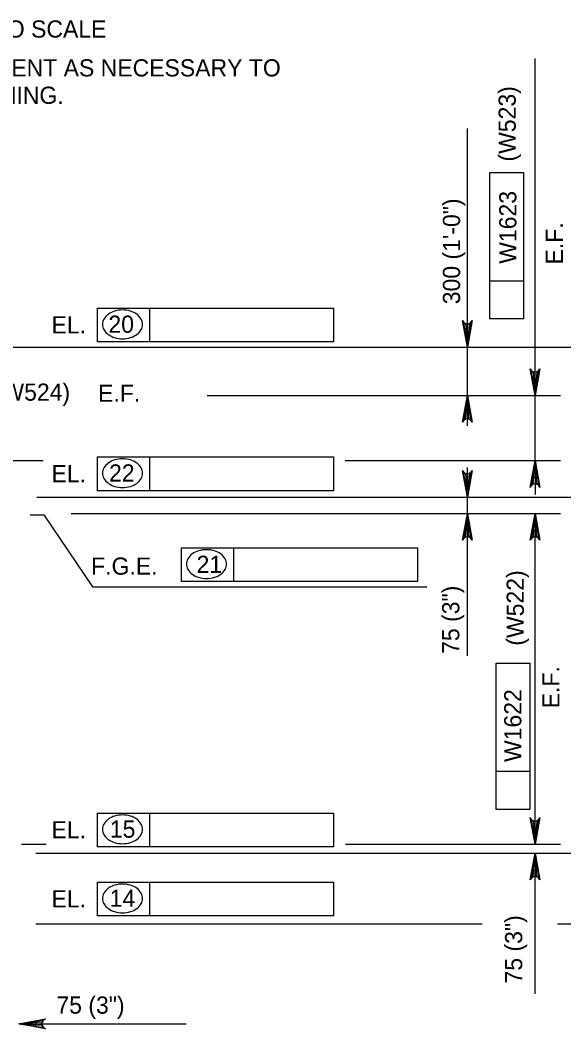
# Model space of a CAD drawing. Extents: x 634540 to 640306, y 296059 to 300275.
# Drawn here: x 639745.6 to 639840.5, y 297355.8 to 297531.8 of the extents above; entities that cross this region are included whole.
import ezdxf

# ---------------------------------------------------------------- set-up
doc = ezdxf.new("R2010")
doc.units = 0
doc.layers.add('3', color=7, linetype='Continuous')
doc.layers.add('4', color=7, linetype='Continuous')

msp = doc.modelspace()

# ---------------------------------------------------------------- linework, layer by layer
at = {"layer": '3'}
msp.add_line((639747.39, 297445.53), (639749.79, 297445.53), dxfattribs=at)
at = {"layer": '4'}
for p, q in [((639835.5, 297476.96), (639835.5, 297525.13)), ((639823.69, 297461.05), (639823.69, 297512.93)), ((639827.61, 297479.7), (639827.61, 297505.24)), ((639827.61, 297505.24), (639833.52, 297505.24)), ((639833.52, 297505.24), (639833.52, 297479.7)), ((639833.52, 297486.29), (639827.61, 297486.29)), ((639759.12, 297481.58), (639800.33, 297481.58)), ((639759.12, 297475.68), (639759.12, 297481.58)), ((639768.29, 297475.68), (639768.29, 297481.58)), ((639800.33, 297481.58), (639800.33, 297475.68)), ((639833.52, 297479.7), (639827.61, 297479.7)), ((639835.5, 297469.29), (639835.5, 297476.96)), ((639676.62, 297474.75), (639870.77, 297474.75)), ((639800.33, 297475.68), (639759.12, 297475.68)), ((639778.3, 297466.33), (639839.93, 297466.33)), ((639835.5, 297454.96), (639835.5, 297466.33)), ((639759.12, 297455.62), (639800.33, 297455.62)), ((639759.12, 297449.71), (639759.12, 297455.62)), ((639768.29, 297449.71), (639768.29, 297455.62)), ((639800.33, 297455.62), (639800.33, 297449.71)), ((639735.66, 297454.96), (639749.63, 297454.96)), ((639802.35, 297454.96), (639839.93, 297454.96)), ((639823.69, 297420.89), (639823.69, 297453.79)), ((639835.5, 297452.01), (639835.5, 297449.06)), ((639748.53, 297448.6), (639858.89, 297448.6)), ((639800.33, 297449.71), (639759.12, 297449.71)), ((639749.79, 297445.53), (639758.26, 297432.92)), ((639754.55, 297445.73), (639839.93, 297445.73)), ((639835.5, 297390.96), (639835.5, 297442.78)), ((639773.78, 297433.85), (639773.78, 297439.76)), ((639773.78, 297439.76), (639814.99, 297439.76)), ((639782.95, 297433.85), (639782.95, 297439.76)), ((639814.99, 297439.76), (639814.99, 297433.85)), ((639758.26, 297432.92), (639816.6, 297432.92)), ((639814.99, 297433.85), (639773.78, 297433.85)), ((639828.7, 297394.11), (639828.7, 297419.65)), ((639828.7, 297419.65), (639834.61, 297419.65)), ((639834.61, 297419.65), (639834.61, 297394.11)), ((639834.61, 297400.7), (639828.7, 297400.7)), ((639834.61, 297394.11), (639828.7, 297394.11)), ((639759.12, 297393.47), (639800.33, 297393.47)), ((639759.12, 297387.57), (639759.12, 297393.47)), ((639768.29, 297387.57), (639768.29, 297393.47)), ((639800.33, 297393.47), (639800.33, 297387.57)), ((639745.89, 297388.01), (639750.16, 297388.01)), ((639800.33, 297387.57), (639759.12, 297387.57)), ((639802.41, 297388.01), (639839.93, 297388.01)), ((639748.37, 297386.47), (639870.77, 297386.47)), ((639835.5, 297361.91), (639835.5, 297383.52)), ((639759.12, 297381.42), (639800.33, 297381.42)), ((639759.12, 297375.51), (639759.12, 297381.42)), ((639768.29, 297375.51), (639768.29, 297381.42)), ((639800.33, 297381.42), (639800.33, 297375.51)), ((639800.33, 297375.51), (639759.12, 297375.51)), ((639748.37, 297374.16), (639826.28, 297374.16)), ((639839.41, 297374.16), (639870.77, 297374.16)), ((639748.33, 297356.69), (639751.28, 297356.69)), ((639751.28, 297356.69), (639774.6, 297356.69))]:
    msp.add_line(p, q, dxfattribs=at)
for points in [[(639823.69, 297474.75), (639822.82, 297479.41), (639823.06, 297479.05), (639823.38, 297478.86), (639823.69, 297478.81), (639824, 297478.86), (639824.32, 297479.05), (639824.56, 297479.41), (639823.69, 297474.75), (639824.32, 297479.05), (639824, 297478.86), (639823.69, 297474.75), (639823.69, 297478.81), (639823.38, 297478.86), (639823.69, 297474.75), (639823.06, 297479.05)], [(639835.5, 297466.33), (639834.63, 297470.99), (639834.88, 297470.64), (639835.19, 297470.45), (639835.5, 297470.4), (639835.81, 297470.45), (639836.13, 297470.64), (639836.37, 297470.99), (639835.5, 297466.33), (639836.13, 297470.64), (639835.81, 297470.45), (639835.5, 297466.33), (639835.5, 297470.4), (639835.19, 297470.45), (639835.5, 297466.33), (639834.88, 297470.64)], [(639823.69, 297466.33), (639824.56, 297461.67), (639824.32, 297462.03), (639824, 297462.22), (639823.69, 297462.27), (639823.38, 297462.22), (639823.06, 297462.03), (639822.82, 297461.67), (639823.69, 297466.33), (639823.06, 297462.03), (639823.38, 297462.22), (639823.69, 297466.33), (639823.69, 297462.27), (639824, 297462.22), (639823.69, 297466.33), (639824.32, 297462.03)], [(639835.5, 297454.96), (639836.37, 297450.3), (639836.13, 297450.66), (639835.81, 297450.85), (639835.5, 297450.9), (639835.19, 297450.85), (639834.88, 297450.66), (639834.63, 297450.3), (639835.5, 297454.96), (639834.88, 297450.66), (639835.19, 297450.85), (639835.5, 297454.96), (639835.5, 297450.9), (639835.81, 297450.85), (639835.5, 297454.96), (639836.13, 297450.66)], [(639823.69, 297448.6), (639822.82, 297453.26), (639823.06, 297452.9), (639823.38, 297452.72), (639823.69, 297452.66), (639824, 297452.72), (639824.32, 297452.9), (639824.56, 297453.26), (639823.69, 297448.6), (639824.32, 297452.9), (639824, 297452.72), (639823.69, 297448.6), (639823.69, 297452.66), (639823.38, 297452.72), (639823.69, 297448.6), (639823.06, 297452.9)], [(639823.69, 297445.73), (639824.56, 297441.07), (639824.32, 297441.43), (639824, 297441.62), (639823.69, 297441.67), (639823.38, 297441.62), (639823.06, 297441.43), (639822.82, 297441.07), (639823.69, 297445.73), (639823.06, 297441.43), (639823.38, 297441.62), (639823.69, 297445.73), (639823.69, 297441.67), (639824, 297441.62), (639823.69, 297445.73), (639824.32, 297441.43)], [(639835.5, 297445.73), (639836.37, 297441.07), (639836.13, 297441.43), (639835.81, 297441.62), (639835.5, 297441.67), (639835.19, 297441.62), (639834.88, 297441.43), (639834.63, 297441.07), (639835.5, 297445.73), (639834.88, 297441.43), (639835.19, 297441.62), (639835.5, 297445.73), (639835.5, 297441.67), (639835.81, 297441.62), (639835.5, 297445.73), (639836.13, 297441.43)], [(639835.5, 297388.01), (639834.63, 297392.67), (639834.88, 297392.31), (639835.19, 297392.12), (639835.5, 297392.07), (639835.81, 297392.12), (639836.13, 297392.31), (639836.37, 297392.67), (639835.5, 297388.01), (639836.13, 297392.31), (639835.81, 297392.12), (639835.5, 297388.01), (639835.5, 297392.07), (639835.19, 297392.12), (639835.5, 297388.01), (639834.88, 297392.31)], [(639835.5, 297386.47), (639836.37, 297381.81), (639836.13, 297382.17), (639835.81, 297382.35), (639835.5, 297382.4), (639835.19, 297382.35), (639834.88, 297382.17), (639834.63, 297381.81), (639835.5, 297386.47), (639834.88, 297382.17), (639835.19, 297382.35), (639835.5, 297386.47), (639835.5, 297382.4), (639835.81, 297382.35), (639835.5, 297386.47), (639836.13, 297382.17)], [(639745.38, 297356.69), (639750.04, 297357.56), (639749.68, 297357.31), (639749.49, 297357), (639749.44, 297356.69), (639749.49, 297356.38), (639749.68, 297356.06), (639750.04, 297355.82), (639745.38, 297356.69), (639749.68, 297356.06), (639749.49, 297356.38), (639745.38, 297356.69), (639749.44, 297356.69), (639749.49, 297357), (639745.38, 297356.69), (639749.68, 297357.31)]]:
    msp.add_lwpolyline(points, dxfattribs=at)
for points in [[(639835.01, 297469.29), (639835.99, 297469.29), (639835.5, 297466.33)], [(639823.2, 297463.38), (639824.18, 297463.38), (639823.69, 297466.33)], [(639835.01, 297452.01), (639835.99, 297452.01), (639835.5, 297454.96)], [(639823.2, 297451.55), (639824.18, 297451.55), (639823.69, 297448.6)], [(639823.2, 297442.78), (639824.18, 297442.78), (639823.69, 297445.73)], [(639835.01, 297442.78), (639835.99, 297442.78), (639835.5, 297445.73)], [(639835.01, 297390.96), (639835.99, 297390.96), (639835.5, 297388.01)], [(639835.01, 297383.52), (639835.99, 297383.52), (639835.5, 297386.47)], [(639748.33, 297357.18), (639748.33, 297356.2), (639745.38, 297356.69)]]:
    msp.add_lwpolyline(points, close=True, dxfattribs=at)
for centre, radius, start, end in [((639762.63, 297478.27), 2.76, 125.6316, 149.9767), ((639763.16, 297477.54), 3.66, 106.5358, 125.6316), ((639763.5, 297476.38), 4.87, 90, 106.5358), ((639763.5, 297476.38), 4.87, 73.4642, 90), ((639763.84, 297477.54), 3.66, 54.3684, 73.4642), ((639764.37, 297478.27), 2.76, 30.0233, 54.3684), ((639761.82, 297478.74), 1.83, 149.9767, 180), ((639761.82, 297478.74), 1.83, 180, 210.0233), ((639765.18, 297478.74), 1.83, 0, 30.0233), ((639765.18, 297478.74), 1.83, 329.9767, 0), ((639762.63, 297479.2), 2.76, 210.0233, 234.3684), ((639763.16, 297479.94), 3.66, 234.3684, 253.4642), ((639763.5, 297481.1), 4.87, 253.4642, 270), ((639763.5, 297481.1), 4.87, 270, 286.5358), ((639763.84, 297479.94), 3.66, 286.5358, 305.6316), ((639764.37, 297479.2), 2.76, 305.6316, 329.9767), ((639763.5, 297450.41), 4.87, 90, 106.5358), ((639763.5, 297450.41), 4.87, 73.4642, 90), ((639761.82, 297452.77), 1.83, 149.9767, 180), ((639762.63, 297452.31), 2.76, 125.6316, 149.9767), ((639763.16, 297451.57), 3.66, 106.5358, 125.6316), ((639763.84, 297451.57), 3.66, 54.3684, 73.4642), ((639764.37, 297452.31), 2.76, 30.0233, 54.3684), ((639765.18, 297452.77), 1.83, 0, 30.0233), ((639761.82, 297452.77), 1.83, 180, 210.0233), ((639762.63, 297453.24), 2.76, 210.0233, 234.3684), ((639764.37, 297453.24), 2.76, 305.6316, 329.9767), ((639765.18, 297452.77), 1.83, 329.9767, 0), ((639763.16, 297453.97), 3.66, 234.3684, 253.4642), ((639763.5, 297455.13), 4.87, 253.4642, 270), ((639763.5, 297455.13), 4.87, 270, 286.5358), ((639763.84, 297453.97), 3.66, 286.5358, 305.6316), ((639778.16, 297434.55), 4.87, 90, 106.5358), ((639778.16, 297434.55), 4.87, 73.4642, 90), ((639776.48, 297436.91), 1.83, 149.9767, 180), ((639777.29, 297436.45), 2.76, 125.6316, 149.9767), ((639777.81, 297435.71), 3.66, 106.5358, 125.6316), ((639778.5, 297435.71), 3.66, 54.3684, 73.4642), ((639779.03, 297436.45), 2.76, 30.0233, 54.3684), ((639779.83, 297436.91), 1.83, 0, 30.0233), ((639776.48, 297436.91), 1.83, 180, 210.0233), ((639777.29, 297437.38), 2.76, 210.0233, 234.3684), ((639779.03, 297437.38), 2.76, 305.6316, 329.9767), ((639779.83, 297436.91), 1.83, 329.9767, 0), ((639777.81, 297438.11), 3.66, 234.3684, 253.4642), ((639778.16, 297439.27), 4.87, 253.4642, 270), ((639778.16, 297439.27), 4.87, 270, 286.5358), ((639778.5, 297438.11), 3.66, 286.5358, 305.6316), ((639762.63, 297390.16), 2.76, 125.6316, 149.9767), ((639763.16, 297389.43), 3.66, 106.5358, 125.6316), ((639763.5, 297388.27), 4.87, 90, 106.5358), ((639763.5, 297388.27), 4.87, 73.4642, 90), ((639763.84, 297389.43), 3.66, 54.3684, 73.4642), ((639764.37, 297390.16), 2.76, 30.0233, 54.3684), ((639761.82, 297390.63), 1.83, 149.9767, 180), ((639761.82, 297390.63), 1.83, 180, 210.0233), ((639765.18, 297390.63), 1.83, 0, 30.0233), ((639765.18, 297390.63), 1.83, 329.9767, 0), ((639762.63, 297391.09), 2.76, 210.0233, 234.3684), ((639763.16, 297391.83), 3.66, 234.3684, 253.4642), ((639763.84, 297391.83), 3.66, 286.5358, 305.6316), ((639764.37, 297391.09), 2.76, 305.6316, 329.9767), ((639763.5, 297392.99), 4.87, 253.4642, 270), ((639763.5, 297392.99), 4.87, 270, 286.5358), ((639762.63, 297378.11), 2.76, 125.6316, 149.9767), ((639763.16, 297377.37), 3.66, 106.5358, 125.6316), ((639763.5, 297376.21), 4.87, 90, 106.5358), ((639763.5, 297376.21), 4.87, 73.4642, 90), ((639763.84, 297377.37), 3.66, 54.3684, 73.4642), ((639764.37, 297378.11), 2.76, 30.0233, 54.3684), ((639761.82, 297378.57), 1.83, 149.9767, 180), ((639761.82, 297378.57), 1.83, 180, 210.0233), ((639765.18, 297378.57), 1.83, 0, 30.0233), ((639765.18, 297378.57), 1.83, 329.9767, 0), ((639762.63, 297379.04), 2.76, 210.0233, 234.3684), ((639763.16, 297379.77), 3.66, 234.3684, 253.4642), ((639763.5, 297380.93), 4.87, 253.4642, 270), ((639763.5, 297380.93), 4.87, 270, 286.5358), ((639763.84, 297379.77), 3.66, 286.5358, 305.6316), ((639764.37, 297379.04), 2.76, 305.6316, 329.9767)]:
    msp.add_arc(centre, radius, start, end, dxfattribs=at)

# ---------------------------------------------------------------- texts
for s, height, p in [('NO SCALE', 3, (639740.41, 297528.78)), ('ADJUST REINFORCEMENT AS NECESSARY TO', 3.0001, (639700.4, 297522)), ('ACCOMMODATE OPENING.', 3.0001, (639700.4, 297517.22)), ('EL.', 3, (639751.1, 297477.16)), ('20', 3, (639761.04, 297477.27)), ('(W524)', 3, (639741.2, 297465.42)), ('E.F.', 3, (639759.24, 297465.23)), ('EL.', 3, (639751.1, 297451.2)), ('22', 3, (639761.15, 297451.31)), ('F.G.E.', 3, (639758.02, 297435.06)), ('21', 3, (639776.43, 297435.37)), ('EL.', 3, (639751.1, 297389.05)), ('15', 3, (639761.29, 297389.17)), ('EL.', 3, (639751.1, 297377)), ('14', 3, (639761.26, 297377.11)), ('75 (3")', 3, (639751.96, 297358.46))]:
    msp.add_text(s, height=height, dxfattribs=at).set_placement(p)
for s, height, p in [('(W523)', 3, (639832.14, 297507.15)), ('W1623', 3, (639832.25, 297489.31)), ('300 (1\'-0")', 3.0001, (639822.42, 297482.25)), ('E.F.', 3, (639840.37, 297489.19)), ('(W522)', 3, (639833.55, 297422.67)), ('75 (3")', 3, (639822.29, 297421.24)), ('E.F.', 3, (639839.77, 297411.75)), ('W1622', 3, (639833.12, 297402.37)), ('75 (3")', 3, (639833.27, 297363.73))]:
    msp.add_text(s, height=height, rotation=90, dxfattribs=at).set_placement(p)

doc.saveas('drawing.dxf')
